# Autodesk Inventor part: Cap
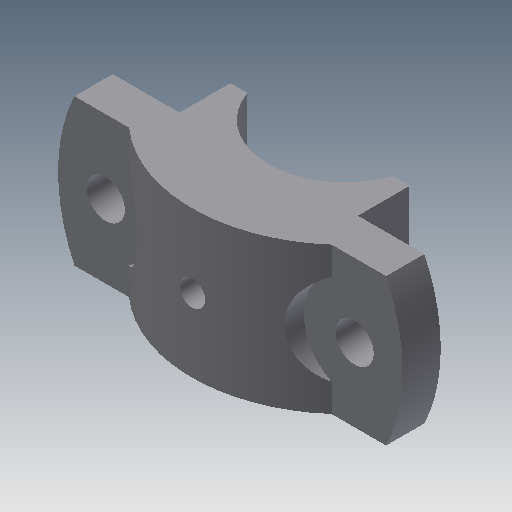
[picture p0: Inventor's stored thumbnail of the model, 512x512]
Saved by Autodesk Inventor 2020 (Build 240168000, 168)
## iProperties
Created: 2009-04
Part Number: Cap
Document SubType Name: Modeling
Designer: Sham
Density: 1 g/cm^3
Material: Generic
Appearance: Default
Author: Sham
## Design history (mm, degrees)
sketch "Sketch1"
  geometry: L1 (-48.857, 23)-(48.857, 23); L2 (48.857, -23)-(-48.857, -23); A1 r 54 centre (0, 0) between (-48.857, 23) and (-48.857, -23); A2 r 54 centre (0, 0) between (48.857, -23) and (48.857, 23); 1 further point
  constraints: 4 end point, 4 point on circle, 2 centre point, 2 coincident, 1 horizontal, 1 parallel, 1 other
  dimensions: "d3" = 54 radius of A1; "d4" = 54 radius of A2; "d5" = 46 distance between parallel lines of L2 L1; "d6" = 23 distance from line of point (0, 0) L1
extrude "Extrusion1" new body sketch "Sketch1" distance "d7" = 12; taper "d8" = 0 deg
sketch "Sketch3"
  geometry: L1 (20.906, 0)-(20.906, -16); L2 (76.906, -0.137)-(76.906, -16.137); L3 (20.906, -16)-(26.23, -16); L4 (71.532, -16.137)-(76.906, -16.137); L5 (76.906, -0.137)-(76.857, 12); L6 (97.714, 0)-(0, 0) reference; L7 (76.857, 12)-(80.606, 12); L8 (17.108, 12)-(20.906, 12); L9 (20.906, 12)-(20.906, 0); L10 (0, 12)-(97.714, 12) reference; A1 r 24 centre (48.857, -24) between (71.532, -16.137) and (26.23, -16); A2 r 48 centre (48.857, -24) between (80.606, 12) and (17.108, 12); 3 further points
  constraints: 16 end point, 4 point on circle, 3 parallel, 3 perpendicular, 2 centre point, 2 coincident, 2 vertical alignment, 1 collinear, 1 midpoint, 1 vertical, 2 other
  dimensions: "d17" = 48 diameter of A1; "d18" = 16 distance of L1.start L1.end; "d19" = 56 distance between parallel lines of L2 L1; "d21" = 8 vertical distance of A1.centre L1.end; "d22" = 48 radius of A2; "d23" = 0 distance from line of L6 L1.start; "d38" = 31.74902 distance of L7.end point (48.857, 12); "d39" = 28 distance from line of point (48.857, 12) L5
extrude "Extrusion2" join sketch "Sketch3" stored distance "d24" = 12; taper "d25" = 0 deg
sketch "Sketch4"
  geometry: 2 further points
  dimensions: "d26" = 78 distance of point (39, 0) point (-39, 0)
hole "Hole1" sketch "Sketch4" at (-39, 0), (39, 0) diameter "d28" = 12; stored, may be unused: countersink angle "d32" = 90 deg, drill point angle "d34" = 118 deg; dims "d29" = 6, "d30" = 4, "d31" = 2, "d33" = 8
sketch "Sketch5"
  geometry: L1 (-31.749, -23)-(-31.749, 23) reference; L2 (-31.749, 14.263)-(-31.749, -14.263); C1 r 6 at (-39, 0) reference; A1 r 16 centre (-39, 0) between (-31.749, -14.263) and (-31.749, 14.263)
  constraints: 2 end point, 2 point on circle, 1 centre point, 1 coincident, 1 collinear, 1 point on line
  dimensions: "d35" = 16 radius of A1
extrude "Extrusion3" cut sketch "Sketch5" distance "d36" = 12; taper "d37" = 0 deg
mirror "Mirror2"
workplane "Work Plane4"
sketch "Sketch6"
  geometry: L1 (-31.749, 0)-(31.749, 0) reference; 1 further point
  dimensions: "d40" = 23 distance from line of L1 point (0, 23)
hole "Hole2" sketch "Sketch6" at (0, 23) diameter "d41" = 6; stored, may be unused: countersink angle "d45" = 90 deg, drill point angle "d47" = 118 deg; dims "d42" = 6, "d43" = 8, "d44" = 16, "d46" = 8
body "Solid1"
